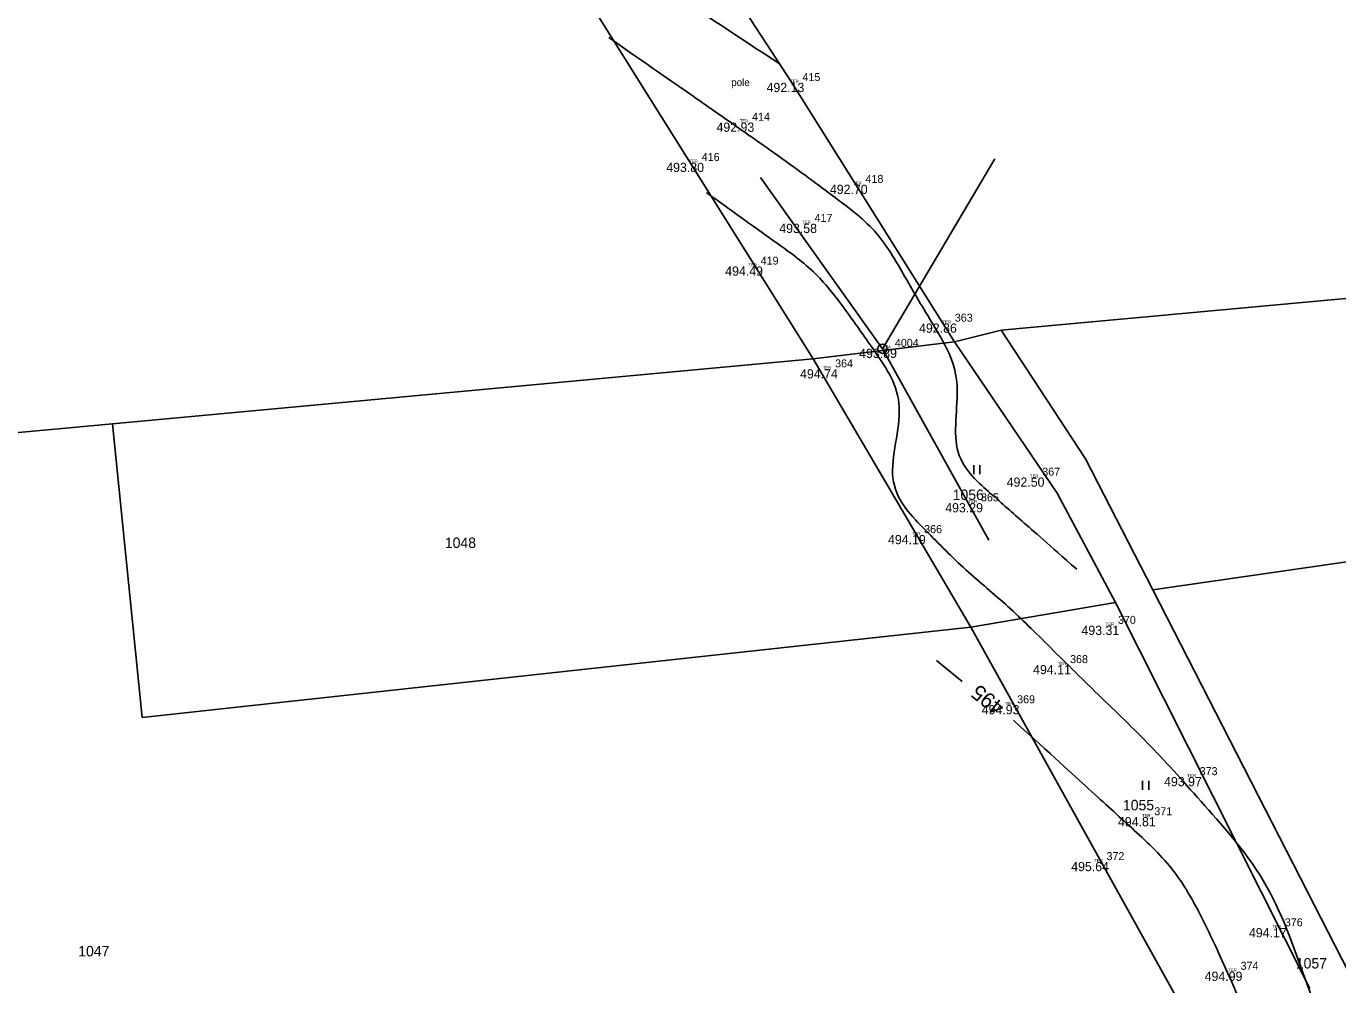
# Model space of a CAD drawing. Extents: x -604848 to -603227, y -1111879 to -1109838.
# Drawn here: x -604101.9 to -603888.8, y -1110343.6 to -1110187.8 of the extents above; entities that cross this region are included whole.
import ezdxf

# ---------------------------------------------------------------- set-up
doc = ezdxf.new("R2010")
doc.units = 0
for name, color, linetype in [('1', 7, 'Continuous'), ('14', 7, 'Continuous'), ('18', 7, 'Continuous'), ('19', 7, 'Continuous'), ('20', 7, 'Continuous'), ('23', 7, 'Continuous'), ('5', 7, 'Continuous'), ('7', 7, 'Continuous'), ('9', 7, 'Continuous'), ('Default', 7, 'Continuous')]:
    doc.layers.add(name, color=color, linetype=linetype)

# ---------------------------------------------------------------- blocks, each defined once
blk = doc.blocks.new('Z3060')
at = {"layer": '23'}
for p, q in [((-0.5, 0), (-0.5, 1.5)), ((0.5, 1.5), (0.5, 0))]:
    blk.add_line(p, q, dxfattribs=at)
blk = doc.blocks.new('POINT_DISPLAY')
at = {"layer": 'Default'}
blk.add_line((0, 0), (0, 0), dxfattribs=at)
blk = doc.blocks.new('Z107')
at = {"layer": '5'}
for radius in [0.75, 0.01]:
    blk.add_circle((0, 0), radius, dxfattribs=at)

msp = doc.modelspace()

# ---------------------------------------------------------------- linework, layer by layer
at = {"layer": '1'}
for p, q in [((-603973.97, -1110241.87), (-604052.4, -1110116.85)), ((-604018.44, -1110133.77), (-603977.54, -1110196.88)), ((-603977.54, -1110196.88), (-603951.04, -1110239.09)), ((-603943.43, -1110237.19), (-603748.02, -1110219.29)), ((-603951.04, -1110239.09), (-603943.43, -1110237.19)), ((-603943.43, -1110237.19), (-603929.76, -1110258.11)), ((-603951.04, -1110239.09), (-603973.97, -1110241.87)), ((-603934.34, -1110263.72), (-603951.04, -1110239.09)), ((-604087.86, -1110252.41), (-603973.97, -1110241.87)), ((-603973.97, -1110241.87), (-603948.38, -1110285.5)), ((-604122.24, -1110255.59), (-604087.86, -1110252.41)), ((-604083, -1110300.15), (-604087.86, -1110252.41)), ((-603929.76, -1110258.11), (-603918.81, -1110279.39)), ((-603918.81, -1110279.39), (-603771.57, -1110258.26)), ((-603924.87, -1110281.49), (-603934.34, -1110263.72)), ((-603918.81, -1110279.39), (-603886.88, -1110341.74)), ((-603924.87, -1110281.49), (-603948.38, -1110285.5)), ((-603893.27, -1110344.22), (-603924.87, -1110281.49)), ((-603948.38, -1110285.5), (-604083, -1110300.15)), ((-603948.38, -1110285.5), (-603913.91, -1110347.53))]:
    msp.add_line(p, q, dxfattribs=at)
at = {"layer": '5'}
for q in [(-603944.46, -1110209.37), (-603982.54, -1110212.4), (-603945.48, -1110271.36)]:
    msp.add_line((-603962.72, -1110240.22), q, dxfattribs=at)
at = {"layer": '7'}
msp.add_line((-603949.77, -1110294.29), (-603953.93, -1110290.91), dxfattribs=at)
for points in [[(-603979.46, -1110193.91), (-603986.93, -1110189), (-603994.4, -1110184.09), (-604001.86, -1110179.18), (-604010.17, -1110173.72), (-604015.87, -1110165.03), (-604021.29, -1110156.53), (-604026.82, -1110147.85), (-604031.5, -1110138.95), (-604035.76, -1110129.71), (-604039.98, -1110120.54), (-604042.18, -1110110.5), (-604046.42, -1110101.41), (-604050.58, -1110092.48), (-604060.04, -1110086.25), (-604063.09, -1110076.83), (-604066.23, -1110067.12), (-604069.37, -1110057.4), (-604072.51, -1110047.68)], [(-603931.16, -1110276.06), (-603935.8, -1110271.98), (-603940.45, -1110267.89), (-603945.1, -1110263.8), (-603952.27, -1110257.5), (-603949.36, -1110244.87), (-603954.28, -1110236.67), (-603958.82, -1110229.12), (-603963.25, -1110221.02), (-603970.32, -1110215.73), (-603975.7, -1110211.71), (-603981.11, -1110207.82), (-603986.59, -1110204), (-603993.46, -1110199.21), (-604000.34, -1110194.43), (-604007.21, -1110189.65)], [(-603832.97, -1110433.54), (-603835.87, -1110430.45), (-603838.77, -1110427.36), (-603841.67, -1110424.27), (-603847.26, -1110418.31), (-603853.48, -1110412.94), (-603859.43, -1110407.36), (-603865.68, -1110401.5), (-603873.96, -1110398.15), (-603879.7, -1110391.45), (-603886.92, -1110383.01), (-603882.86, -1110369.76), (-603887.08, -1110359.85), (-603893.83, -1110344.03), (-603899.3, -1110326.95), (-603910.93, -1110313.84), (-603919.05, -1110304.7), (-603927.68, -1110296.49), (-603936.23, -1110288.01), (-603942.66, -1110281.65), (-603949.71, -1110275.91), (-603956.03, -1110269.41), (-603962.97, -1110262.28), (-603958.28, -1110248.85), (-603963.99, -1110240.66), (-603968.51, -1110234.18), (-603973.41, -1110227.7), (-603979.81, -1110223.11), (-603983.65, -1110220.36), (-603987.5, -1110217.6), (-603991.34, -1110214.85)], [(-603847.4, -1110438.23), (-603849.93, -1110435.65), (-603852.46, -1110433.06), (-603854.99, -1110430.47), (-603859.22, -1110426.15), (-603863.16, -1110421.54), (-603867.31, -1110417.14), (-603872.27, -1110411.88), (-603879.33, -1110409.19), (-603884.37, -1110403.69), (-603891.25, -1110396.18), (-603895.06, -1110386.94), (-603898.56, -1110377.63), (-603902.93, -1110366.04), (-603901.59, -1110352.93), (-603906.69, -1110341.58), (-603910.59, -1110332.9), (-603915.37, -1110324.38), (-603922.34, -1110318.03), (-603928.71, -1110312.22), (-603935.08, -1110306.41), (-603941.45, -1110300.6)]]:
    msp.add_open_spline(points, degree=3, dxfattribs=at)

# ---------------------------------------------------------------- block references
at = {"layer": '18'}
for p in [(-603977.73, -1110197.01), (-603985.92, -1110203.46), (-603994.1, -1110210), (-603967.49, -1110213.56), (-603975.77, -1110219.91), (-603984.52, -1110226.85), (-603952.98, -1110236.12), (-603962.72, -1110240.22), (-603972.43, -1110243.55), (-603938.77, -1110261.15), (-603948.73, -1110265.32), (-603957.96, -1110270.49), (-603926.47, -1110285.24), (-603934.25, -1110291.62), (-603942.85, -1110298.15), (-603913.19, -1110309.83), (-603920.56, -1110316.35), (-603928.33, -1110323.64), (-603899.36, -1110334.4), (-603906.55, -1110341.47)]:
    msp.add_blockref('POINT_DISPLAY', p, dxfattribs=at)
at = {"layer": '23'}
for p in [(-603947.4, -1110260.62), (-603919.98, -1110311.93)]:
    msp.add_blockref('Z3060', p, dxfattribs=at)
at = {"layer": '5'}
msp.add_blockref('Z107', (-603962.72, -1110240.22), dxfattribs=at)

# ---------------------------------------------------------------- texts
at = {"layer": '14'}
for s, p in [('1056', (-603951.32, -1110264.81)), ('1048', (-604033.84, -1110272.61)), ('1055', (-603923.66, -1110315.25)), ('1047', (-604093.41, -1110338.99)), ('1057', (-603895.57, -1110340.96))]:
    msp.add_text(s, height=1.7, dxfattribs=at).set_placement(p)
at = {"layer": '18'}
for s, p in [('TER', (-603977.73, -1110197.01)), ('TER', (-603985.92, -1110203.46)), ('TER', (-603994.1, -1110210)), ('TER', (-603967.49, -1110213.56)), ('TER', (-603975.77, -1110219.91)), ('TER', (-603984.52, -1110226.85)), ('TER', (-603952.98, -1110236.12)), ('STA', (-603962.72, -1110240.22)), ('TER', (-603972.43, -1110243.55)), ('TER', (-603938.77, -1110261.15)), ('TER', (-603948.73, -1110265.32)), ('TER', (-603957.96, -1110270.49)), ('TER', (-603926.47, -1110285.24)), ('TER', (-603934.25, -1110291.62)), ('TER', (-603942.85, -1110298.15)), ('TER', (-603913.19, -1110309.83)), ('TER', (-603920.56, -1110316.35)), ('TER', (-603928.33, -1110323.64)), ('TER', (-603899.36, -1110334.4)), ('TER', (-603906.55, -1110341.47))]:
    msp.add_text(s, height=0.5, dxfattribs=at).set_placement(p)
at = {"layer": '19'}
for s, p in [('415', (-603975.73, -1110196.71)), ('414', (-603983.92, -1110203.16)), ('416', (-603992.1, -1110209.7)), ('418', (-603965.49, -1110213.26)), ('417', (-603973.77, -1110219.61)), ('419', (-603982.52, -1110226.55)), ('363', (-603950.98, -1110235.82)), ('4004', (-603960.72, -1110239.92)), ('364', (-603970.43, -1110243.25)), ('367', (-603936.77, -1110260.85)), ('365', (-603946.73, -1110265.02)), ('366', (-603955.96, -1110270.19)), ('370', (-603924.47, -1110284.94)), ('368', (-603932.25, -1110291.32)), ('369', (-603940.85, -1110297.85)), ('373', (-603911.19, -1110309.53)), ('371', (-603918.56, -1110316.05)), ('372', (-603926.33, -1110323.34)), ('376', (-603897.36, -1110334.1)), ('374', (-603904.55, -1110341.17))]:
    msp.add_text(s, height=1.3, dxfattribs=at).set_placement(p)
at = {"layer": '20'}
for s, p in [('492.13 ', (-603981.57, -1110198.51)), ('492.93 ', (-603989.7, -1110204.96)), ('493.80 ', (-603997.87, -1110211.5)), ('492.70 ', (-603971.28, -1110215.06)), ('493.58 ', (-603979.51, -1110221.41)), ('494.49 ', (-603988.29, -1110228.35)), ('492.86 ', (-603956.79, -1110237.62)), ('493.89 ', (-603966.52, -1110241.72)), ('494.74 ', (-603976.13, -1110245.05)), ('492.50 ', (-603942.55, -1110262.65)), ('493.29 ', (-603952.54, -1110266.82)), ('494.19 ', (-603961.84, -1110271.99)), ('493.31 ', (-603930.4, -1110286.74)), ('494.11 ', (-603938.26, -1110293.12)), ('494.93 ', (-603946.61, -1110299.65)), ('493.97 ', (-603916.98, -1110311.33)), ('494.81 ', (-603924.47, -1110317.85)), ('495.64 ', (-603932.07, -1110325.14)), ('494.17 ', (-603903.19, -1110335.9)), ('494.99 ', (-603910.38, -1110342.97))]:
    msp.add_text(s, height=1.5, dxfattribs=at).set_placement(p)
at = {"layer": '7'}
msp.add_text('495', height=2.5, rotation=141.3, dxfattribs=at).set_placement((-603942.67, -1110298.12))
at = {"layer": '9'}
msp.add_text('pole', height=1.2, dxfattribs=at).set_placement((-603987.32, -1110197.53))

doc.saveas('drawing.dxf')
